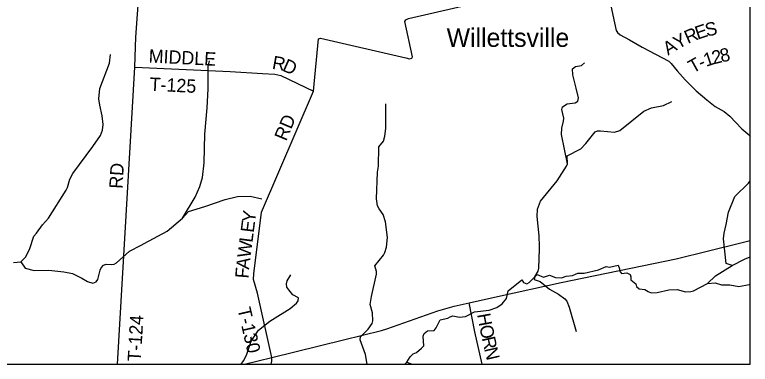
# Model space of a CAD drawing. Extents: x 0 to 1052, y -194 to 246.
# Drawn here: x 5.648 to 8.782, y 14.205 to 15.696 of the extents above; entities that cross this region are included whole.
import ezdxf

# ---------------------------------------------------------------- set-up
doc = ezdxf.new("R2010")
doc.units = 0
for name, color, linetype in [('GM_X_Corporation', 7, 'Continuous'), ('GM_X_County_Road', 7, 'Continuous'), ('GM_X_Minor_River', 7, 'Continuous'), ('GM_X_State_Route', 7, 'Continuous'), ('GM_X_Township_Road', 7, 'Continuous'), ('GM_X_Township_Road_Text', 7, 'Continuous'), ('GM_X_Unincorporated_Text', 7, 'Continuous')]:
    doc.layers.add(name, color=color, linetype=linetype)

msp = doc.modelspace()

# ---------------------------------------------------------------- linework, layer by layer
at = {"layer": 'GM_X_Corporation'}
for points in [[(2.3779, 14.2055), (8.7822, 14.2055), (8.7822, 20.435)], [(5.491, 17.9457), (5.1788, 17.6981), (4.2749, 17.0262), (3.6964, 16.595), (3.6869, 16.5875), (3.6921, 16.5787), (4.0068, 16.0455), (4.1203, 15.8533), (4.4065, 15.3682), (5.0927, 14.2055), (8.7822, 14.2055), (8.7822, 19.8853)]]:
    msp.add_lwpolyline(points, dxfattribs=at)
at = {"layer": 'GM_X_County_Road'}
msp.add_line((6.6263, 14.2055), (6.7438, 14.2346), dxfattribs=at)
for points in [[(6.7438, 14.2346), (7.0485, 14.3103), (7.2113, 14.3501), (7.2339, 14.3571), (7.4508, 14.4334), (7.5197, 14.4527), (7.5849, 14.4676), (7.7049, 14.4949), (7.9765, 14.5549), (8.467, 14.6558), (8.7418, 14.7229), (8.7822, 14.7328)], [(6.7403, 14.2055), (6.7435, 14.2193), (6.7438, 14.2346)]]:
    msp.add_lwpolyline(points, dxfattribs=at)
at = {"layer": 'GM_X_Minor_River'}
msp.add_line((7.319, 14.2142), (7.3416, 14.2055), dxfattribs=at)
for points in [[(5.6425, 14.6401), (5.6739, 14.6419), (5.6947, 14.6637), (5.7118, 14.6998), (5.7298, 14.7523), (5.7402, 14.7643), (5.766, 14.8008), (5.7917, 14.8289), (5.8671, 14.9474), (5.8725, 14.9587), (5.8832, 14.9942), (5.896, 15.0194), (5.9814, 15.1336), (6.0135, 15.1814), (6.0221, 15.2032), (6.025, 15.2279), (6.021, 15.2651), (6.0106, 15.3107), (6.0068, 15.3381), (6.0107, 15.3809), (6.0519, 15.4892), (6.0554, 15.526)], [(5.6739, 14.6419), (5.6921, 14.6159), (5.7314, 14.6059), (5.793, 14.6074), (5.8569, 14.5993), (5.8939, 14.592), (5.9333, 14.5733), (5.9577, 14.5582), (5.9811, 14.5518), (5.9952, 14.5569), (6.0021, 14.5667), (6.0121, 14.6064), (6.0164, 14.6166), (6.0267, 14.6286), (6.0374, 14.6322), (6.0601, 14.6304), (6.0722, 14.6325), (6.0817, 14.6381), (6.1365, 14.6878), (6.186, 14.7133), (6.1993, 14.7208), (6.2976, 14.7726), (6.3623, 14.829), (6.4164, 14.9185), (6.437, 14.963), (6.4485, 15.0019), (6.4546, 15.0644), (6.4573, 15.1873), (6.4682, 15.2987), (6.4723, 15.3794), (6.4728, 15.3915), (6.4716, 15.475), (6.4772, 15.4996)], [(7.3095, 14.2055), (7.319, 14.2142), (7.3333, 14.2371), (7.3456, 14.2498), (7.3597, 14.2561), (7.3815, 14.2744), (7.3918, 14.2845), (7.3878, 14.3248), (7.3925, 14.3372), (7.4063, 14.348), (7.4346, 14.3496), (7.4435, 14.3604), (7.4613, 14.3951), (7.4932, 14.4019), (7.5027, 14.4078), (7.5153, 14.4115), (7.5424, 14.4058), (7.569, 14.4092), (7.607, 14.4285), (7.6688, 14.4368), (7.7015, 14.4477), (7.7244, 14.463), (7.7428, 14.4859), (7.7501, 14.5188), (7.8082, 14.5658), (7.8164, 14.5547), (7.8307, 14.548), (7.8402, 14.5536), (7.8647, 14.5787), (7.8783, 14.6028), (7.8815, 14.6157), (7.8833, 14.6976), (7.8838, 14.7082), (7.8829, 14.7533), (7.8741, 14.8361), (7.8749, 14.8664), (7.8886, 14.9004), (7.9593, 14.9871), (7.9994, 15.0503), (8.0034, 15.0609), (7.9777, 15.1848), (7.9785, 15.2129), (7.9868, 15.2424), (7.987, 15.2545), (7.9791, 15.2921), (7.9815, 15.3035), (8.0014, 15.3165), (8.0366, 15.3202), (8.0469, 15.3281), (8.0505, 15.3417), (8.0401, 15.3835), (8.0257, 15.4402), (8.0241, 15.4653), (8.0371, 15.475), (8.0636, 15.4799), (8.0751, 15.4904)], [(7.1499, 14.2055), (7.1431, 14.2468), (7.1201, 14.3101), (7.1207, 14.3229), (7.1544, 14.3555), (7.171, 14.3799), (7.1738, 14.3909), (7.1723, 14.4243), (7.1626, 14.4605), (7.1687, 14.4945), (7.1896, 14.5891), (7.1893, 14.6012), (7.1821, 14.6259), (7.2194, 14.6702), (7.2248, 14.6823), (7.2323, 14.7053), (7.2359, 14.7458), (7.228, 14.8131), (7.2175, 14.8447), (7.2007, 14.8681), (7.1941, 14.8818), (7.1896, 14.9107), (7.1941, 15.0248), (7.1974, 15.0505), (7.1989, 15.1332), (7.2196, 15.1576), (7.2252, 15.178), (7.2286, 15.2109), (7.2291, 15.2223), (7.2292, 15.3156)], [(8.0034, 15.0609), (8.0015, 15.095), (8.0605, 15.1242), (8.0816, 15.1467), (8.1205, 15.197), (8.1311, 15.201), (8.1436, 15.2009), (8.2029, 15.1948), (8.2257, 15.2025), (8.329, 15.2849), (8.3617, 15.2997), (8.4125, 15.3089), (8.4479, 15.3255)], [(8.7055, 14.6266), (8.6796, 14.6353), (8.6684, 14.7401), (8.6706, 14.7647), (8.6794, 14.8014), (8.69, 14.8547), (8.7165, 14.9215), (8.774, 14.978), (8.7822, 14.9881)], [(6.3623, 14.829), (6.3887, 14.8575), (6.4582, 14.8782), (6.5441, 14.9085), (6.5965, 14.9204), (6.6506, 14.9223), (6.7008, 14.911)], [(7.8647, 14.5787), (7.8743, 14.5881), (7.901, 14.5771), (7.9265, 14.5855), (7.9524, 14.5749), (7.9782, 14.5742), (7.9975, 14.5815), (8.0244, 14.5834), (8.0378, 14.5901), (8.048, 14.5945), (8.0745, 14.5942), (8.136, 14.6089), (8.1687, 14.6225), (8.1827, 14.6201), (8.2198, 14.6276), (8.2242, 14.6131), (8.2248, 14.6036), (8.233, 14.5925), (8.2561, 14.5956), (8.27, 14.5886), (8.2737, 14.5779), (8.2727, 14.5654), (8.2941, 14.5488), (8.2974, 14.5378), (8.3086, 14.5278), (8.3335, 14.5248), (8.3466, 14.5155), (8.3602, 14.5104), (8.3852, 14.5116), (8.4345, 14.5231), (8.4701, 14.5246), (8.5062, 14.5142), (8.5286, 14.5155), (8.5396, 14.5191), (8.6001, 14.5502), (8.6335, 14.5824), (8.7055, 14.6266), (8.757, 14.6536), (8.7822, 14.6636)], [(6.6125, 14.2055), (6.6222, 14.2199), (6.6354, 14.2447), (6.6547, 14.3036), (6.686, 14.351), (6.7353, 14.3894), (6.746, 14.3961), (6.8222, 14.4433), (6.8482, 14.4657), (6.8552, 14.4759), (6.8572, 14.4887), (6.8332, 14.5012), (6.8153, 14.5223), (6.8075, 14.5341), (6.8054, 14.549), (6.8094, 14.561), (6.8248, 14.587)], [(7.8647, 14.5787), (7.8615, 14.5666), (7.8872, 14.5583), (7.9261, 14.5259), (7.9655, 14.5042), (7.9921, 14.4845), (7.9999, 14.4745), (8.0102, 14.449), (8.0399, 14.3454)], [(8.6001, 14.5502), (8.6327, 14.5524), (8.6591, 14.5441), (8.6954, 14.544), (8.7339, 14.5371), (8.7779, 14.5456), (8.7822, 14.5461)]]:
    msp.add_lwpolyline(points, dxfattribs=at)
at = {"layer": 'GM_X_State_Route'}
msp.add_lwpolyline([(8.1841, 15.7549), (8.1962, 15.694), (8.2113, 15.6293), (8.2166, 15.6198), (8.2275, 15.6106), (8.2673, 15.5887), (8.321, 15.5575), (8.4354, 15.4977), (8.4447, 15.4888), (8.4702, 15.4567), (8.5043, 15.4183), (8.5512, 15.3721), (8.5975, 15.3331), (8.6326, 15.305), (8.6708, 15.2828), (8.6947, 15.2637), (8.7456, 15.2098), (8.7799, 15.1805), (8.7822, 15.1782)], dxfattribs=at)
at = {"layer": 'GM_X_Township_Road'}
for points in [[(6.0855, 14.2055), (6.1602, 15.4723), (6.1603, 15.4735), (6.1641, 15.6003), (6.206, 16.1909)], [(6.7438, 14.2346), (6.6817, 14.5094), (6.665, 14.5677), (6.6668, 14.5919), (6.7, 14.8539), (6.9203, 15.3695), (6.943, 15.5938), (6.9506, 15.5955), (7.3148, 15.5122), (7.3295, 15.5084), (7.3402, 15.5104), (7.3434, 15.5171), (7.3102, 15.6666), (7.3146, 15.6748), (7.3261, 15.6802), (7.8327, 15.7978)], [(6.1602, 15.4723), (6.5656, 15.4533), (6.7033, 15.446), (6.7563, 15.4422), (6.7824, 15.4376), (6.9203, 15.3695)], [(7.64, 14.2055), (7.6086, 14.3446), (7.5849, 14.4676)]]:
    msp.add_lwpolyline(points, dxfattribs=at)

# ---------------------------------------------------------------- texts
at = {"layer": 'GM_X_Township_Road_Text'}
for s, height, rotation, p in [('E', 0.0568, 18.4634, (8.5576, 15.5892)), ('S', 0.0568, 12.9432, (8.5966, 15.6022)), ('Y', 0.0568, 29.4114, (8.4739, 15.5473)), ('R', 0.0568, 23.3744, (8.516, 15.5711)), ('A', 0.0568, 31.4557, (8.4317, 15.5215)), ('MIDDLE', 0.05682, 357.1731, (6.2178, 15.4923)), ('2', 0.0568, 13.5737, (8.6254, 15.4843)), ('8', 0.0568, 12.0846, (8.6591, 15.4924)), ('R', 0.0568, 350.068, (6.7421, 15.4657)), ('T', 0.0568, 29.2128, (8.5376, 15.4446)), ('1', 0.0568, 18.8044, (8.5936, 15.4734)), ('D', 0.0568, 335.9617, (6.7846, 15.4588)), ('-', 0.0568, 23.1104, (8.5732, 15.4646)), ('T-125', 0.05682, 357.1941, (6.2219, 15.3722)), ('RD', 0.05682, 67.1899, (6.8044, 15.1544)), ('RD', 0.05682, 86.5168, (6.1069, 14.9529)), ('Y', 0.0568, 81.9284, (6.6715, 14.8067)), ('E', 0.0568, 82.7618, (6.6662, 14.7648)), ('L', 0.0568, 82.7639, (6.6608, 14.7226)), ('W', 0.0568, 82.7624, (6.6525, 14.6573)), ('A', 0.0568, 83.0028, (6.6464, 14.6077)), ('F', 0.0568, 85.5102, (6.6435, 14.5702)), ('T-130', 0.05682, 283.0157, (6.5965, 14.4419)), ('H', 0.0568, 280.4319, (7.6179, 14.418)), ('T-124', 0.05682, 86.6338, (6.1851, 14.2158)), ('O', 0.0568, 281.792, (7.6272, 14.3674)), ('R', 0.0568, 282.8014, (7.6377, 14.3174)), ('N', 0.0568, 282.881, (7.648, 14.2718))]:
    msp.add_text(s, height=height, rotation=rotation, dxfattribs=at).set_placement(p)
at = {"layer": 'GM_X_Unincorporated_Text'}
msp.add_text('Willettsville', height=0.078977, rotation=0, dxfattribs=at).set_placement((7.4884, 15.559))

doc.saveas('drawing.dxf')
